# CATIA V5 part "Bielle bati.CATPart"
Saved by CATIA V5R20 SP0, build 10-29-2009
Part number: Bielle bati
Publications: "Arête", "Arête1"
Bounding box of the stored display mesh (mm): x -10 to 10, y 151.981 to 236.617, z 103.711 to 130.504
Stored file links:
  C:\Users\thinkmotion1\Desktop\Khaled_IAO_Pack2\IAO_2010_1412_jclement\Non_Optimise\Bielle bati.CATPart
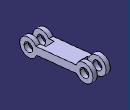
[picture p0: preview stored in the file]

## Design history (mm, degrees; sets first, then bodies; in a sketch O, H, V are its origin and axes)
Body1 (main body)
  Sketch1 on yz-plane, origin (0, 0, 0), H (0, 1, 0), V (0, 0, 1)
    arc A1 centre (161.9769, 113.7106) radius 10 from (170.5374, 118.8795) to (171.4249, 110.4341) ccw
    point P1 (161.9769, 113.7106)
    arc A2 centre (226.621, 120.5037) radius 10 from (218.0605, 115.3348) to (217.173, 123.7802) ccw
    point P2 (226.621, 120.5037)
    construction line L1 (144.6861, 111.8936) -> (235.7017, 121.4579)
    line L2 (170.5374, 118.8795) -> (217.173, 123.7802)
    line L3 (171.4249, 110.4341) -> (218.0605, 115.3348)
    radius A1 = 10
    radius A2 = 10
    distance P2 P1 = 65
    coincidence: L1 P2, P1 L1
    parallelism: L2 L1, L3 L1
    symmetry: L3 L2 L1
  Pad1: profile Sketch1, direction (1, 0, 0), length 10, mirrored extent
  Sketch2 on end face of Pad1, origin (10, 0, 0), H (0, 1, 0), V (0, 0, 1)
    circle A1 centre (161.9769, 113.7106) radius 5
    circle A2 centre (226.621, 120.5037) radius 5
    reference projected arc E1 centre (226.621, 120.5037) radius 10 from (218.0605, 115.3348) to (217.173, 123.7802) ccw from edge [face of Pad1 from Sketch1.A2 | end face of Pad1]
    reference projected arc E2 centre (161.9769, 113.7106) radius 10 from (170.5374, 118.8795) to (171.4249, 110.4341) ccw from edge [face of Pad1 from Sketch1.A1 | end face of Pad1]
    radius A2 = 5
    radius A1 = 5
    concentricity: A2 E1, A1 E2
  Pocket1: profile Sketch2, direction (-1, 0, 0), through (limit type 6)
  Sketch3 on face of Pad1 from Sketch1.L2, origin (0, -10.4933, 99.8559), H (1, 0, 0), V (0, 0.9945, 0.1045)
    line L1 (-5, 188.5858) -> (5, 188.5858)
    line L2 (5, 188.5858) -> (5, 160.5858)
    line L3 (5, 160.5858) -> (-5, 160.5858)
    line L4 (-5, 160.5858) -> (-5, 188.5858)
    reference intersected line E1 through (0, 0) direction (0, 1) from yz-plane
    point P5 (-5, 248.6738)
    line L5 (-5, 248.6738) -> (5, 248.6738)
    line L6 (5, 248.6738) -> (5, 226.6738)
    line L7 (5, 226.6738) -> (-5, 226.6738)
    line L8 (-5, 226.6738) -> (-5, 248.6738)
    point P7 (5, 226.6738)
    length L2 = 28
    length L1 = 10
    length L6 = 22
    horizontal: L1 H, L3 H, L5 H, L7 H
    vertical: L2 V, L4 V, L6 V, L8 V
    symmetry: L2 L4 E1
    coincidence: P5 L4, P7 L2
  Pocket2: profile Sketch3, direction (0, 0.1045, -0.9945), length 16, opposite side length 9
